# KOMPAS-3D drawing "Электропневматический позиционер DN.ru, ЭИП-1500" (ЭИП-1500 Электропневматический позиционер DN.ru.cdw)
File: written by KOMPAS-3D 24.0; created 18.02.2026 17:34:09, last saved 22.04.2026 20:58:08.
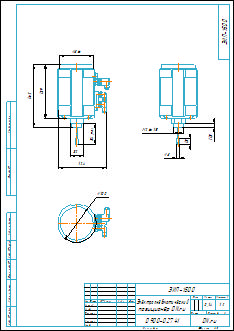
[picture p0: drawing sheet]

Document properties: Автор: R2D2; Форматы листов документа: A3; Полное имя файла: ЭИП-1500 Электропневматический позиционер DN.ru.m3d; Масса: 0.14; Наименование: Электропневматический позиционер DN.ru; Количество листов документа: 1; Примечание: D900-02741

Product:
- Body: Тело 2  | qty 1
    Масса: 8.188644
- Part/product: Электропневматический позиционер DN.ru  | designation ЭИП-1500
    Масса: 0.14
    Раздел спецификации: Прочие изделия
    Примечание: D900-02741

Views: Проекционный вид 2
Referenced files in E:\Работа\Зайцев\Аксессуары для пневмоприводов\Электропневматические позиционеры DN.ru\ЭИП Электропневматический позиционер DN.ru\ЭИП-1500 Электропневматический позиционер DN.ru\5-25\: ЭИП-1500 Электропневматический позиционер DN.ru.m3d
Referenced files in E:\Работа\Зайцев\Для компаса\: чертеж DN.ru А3.cdt
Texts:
  ЭИП-1500
  чертеж DN.ru А3.cdt
  Электропневматический
  позиционер DN.ru
  Электропневматический позиционер DN.ru
  ЭИП-1500 Электропневматический позиционер DN.ru
Dimensions and other numbers on the sheet: 0; 3; 4; 15; 11,5; 8; 26; 1:2; 1; 2; 0,14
